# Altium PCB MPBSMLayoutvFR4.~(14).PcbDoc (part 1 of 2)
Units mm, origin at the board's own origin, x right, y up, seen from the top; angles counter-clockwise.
Board outline 131.7 x 110.39 mm, 4 copper layers (Top Layer, Power, GroundPlane, Bottom Layer), stack 2.286 mm thick; 156 components, 77 nets, 429 pads, 117 vias.
Unrouted connection lines stored in the file: 25.
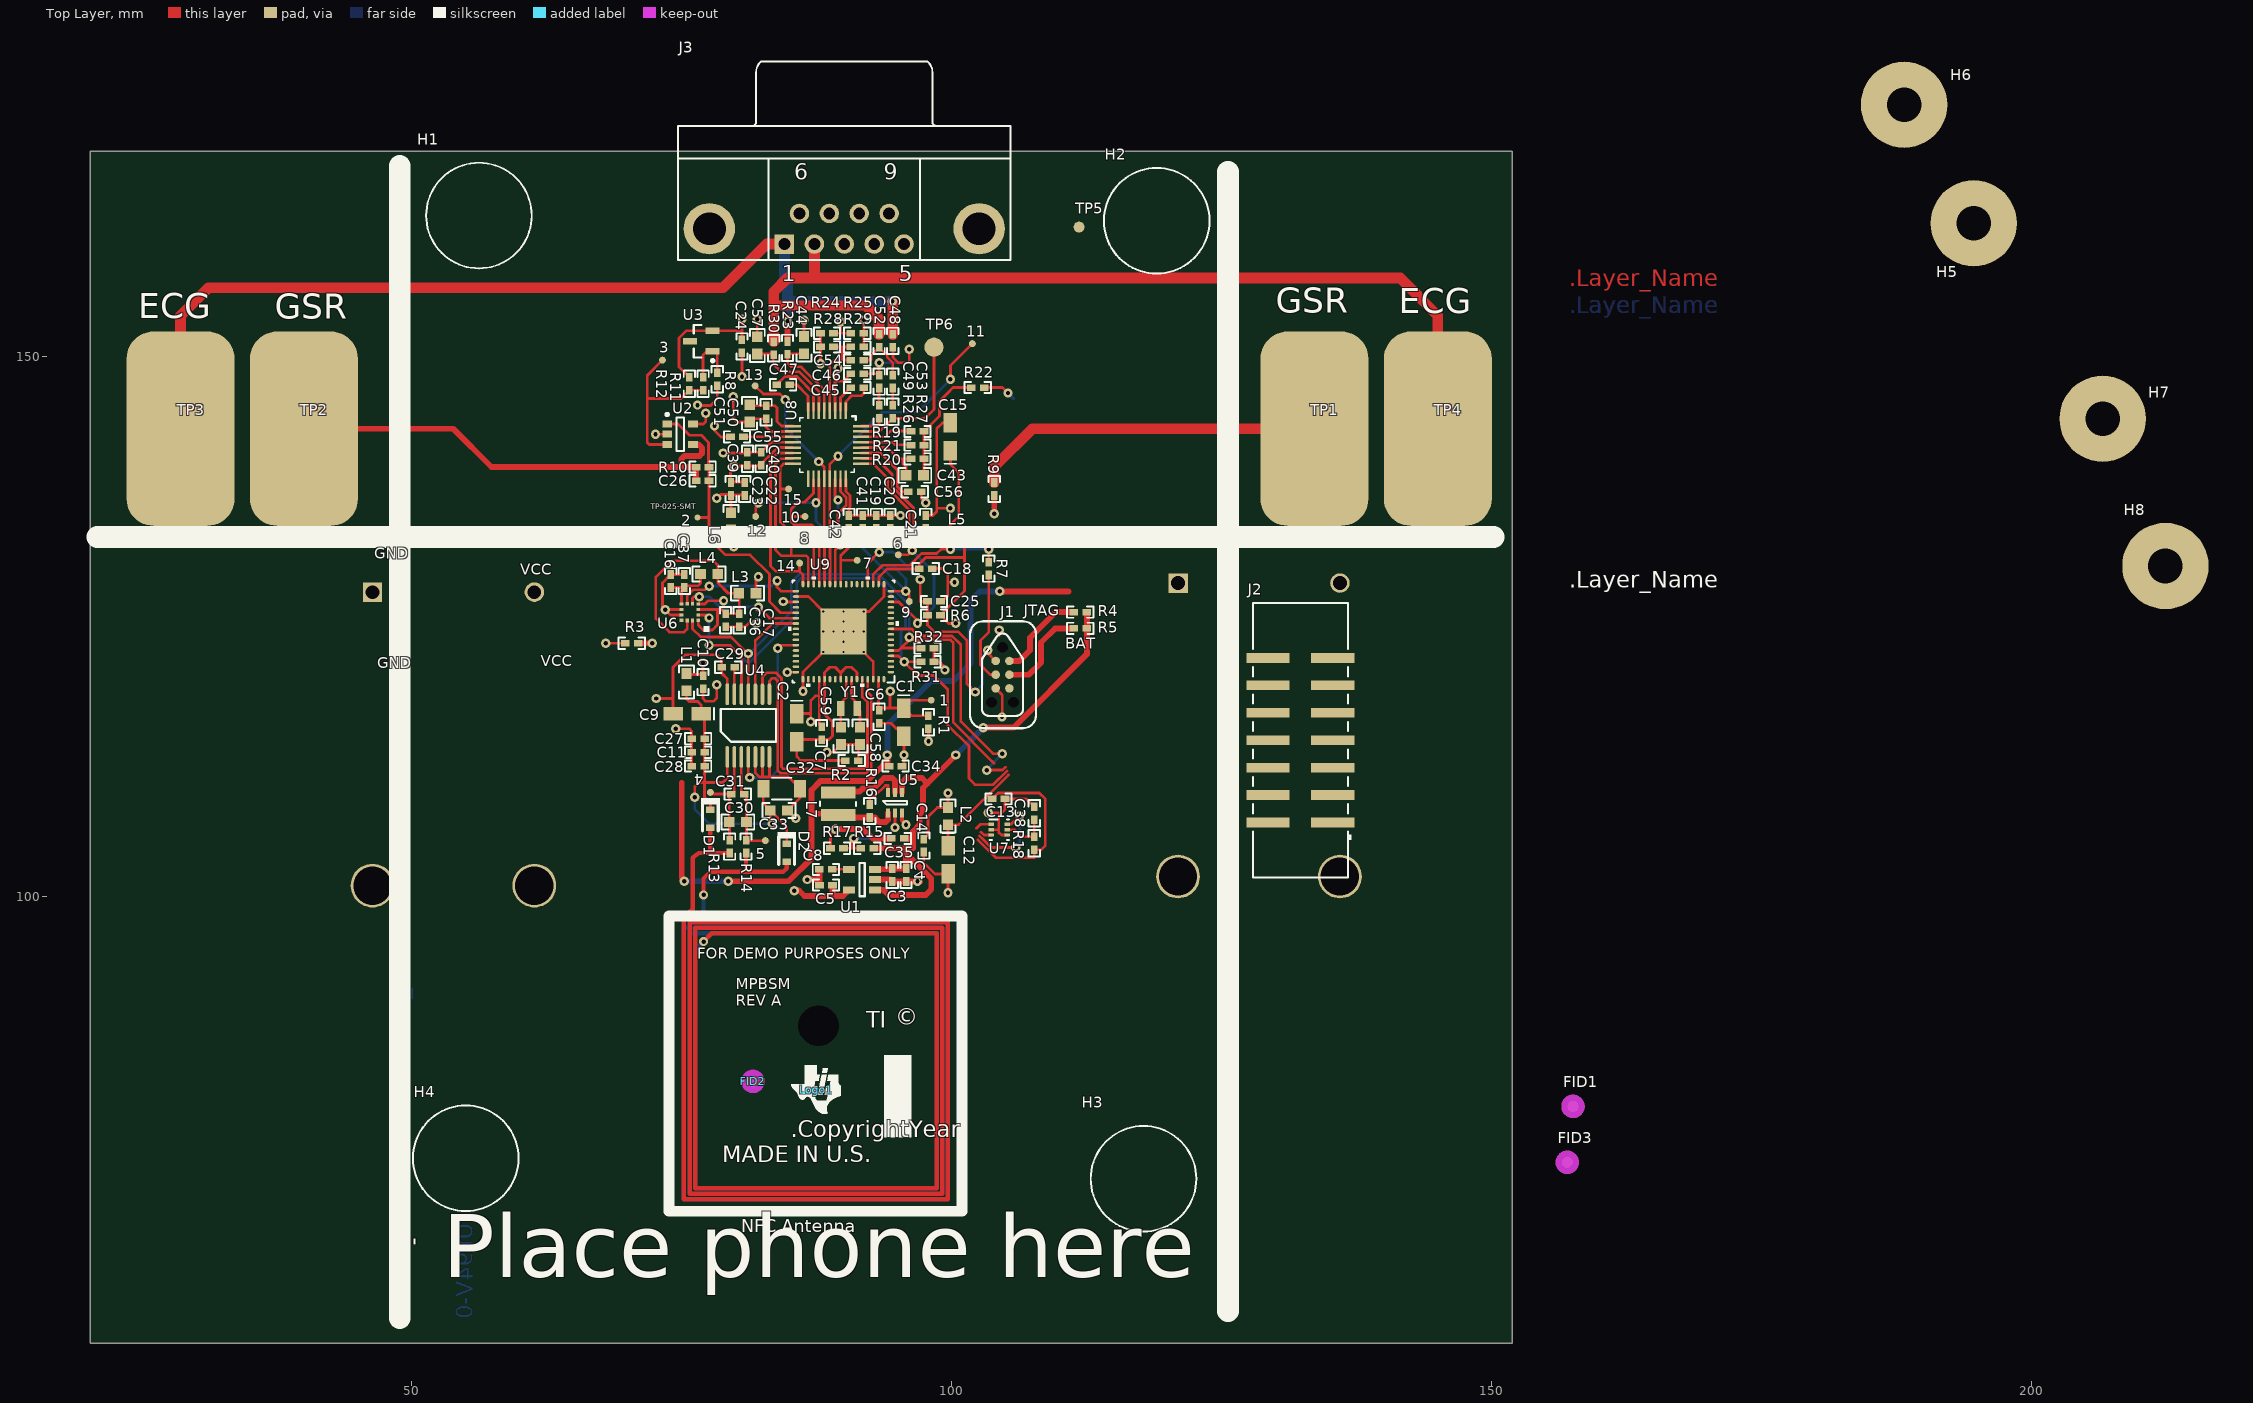
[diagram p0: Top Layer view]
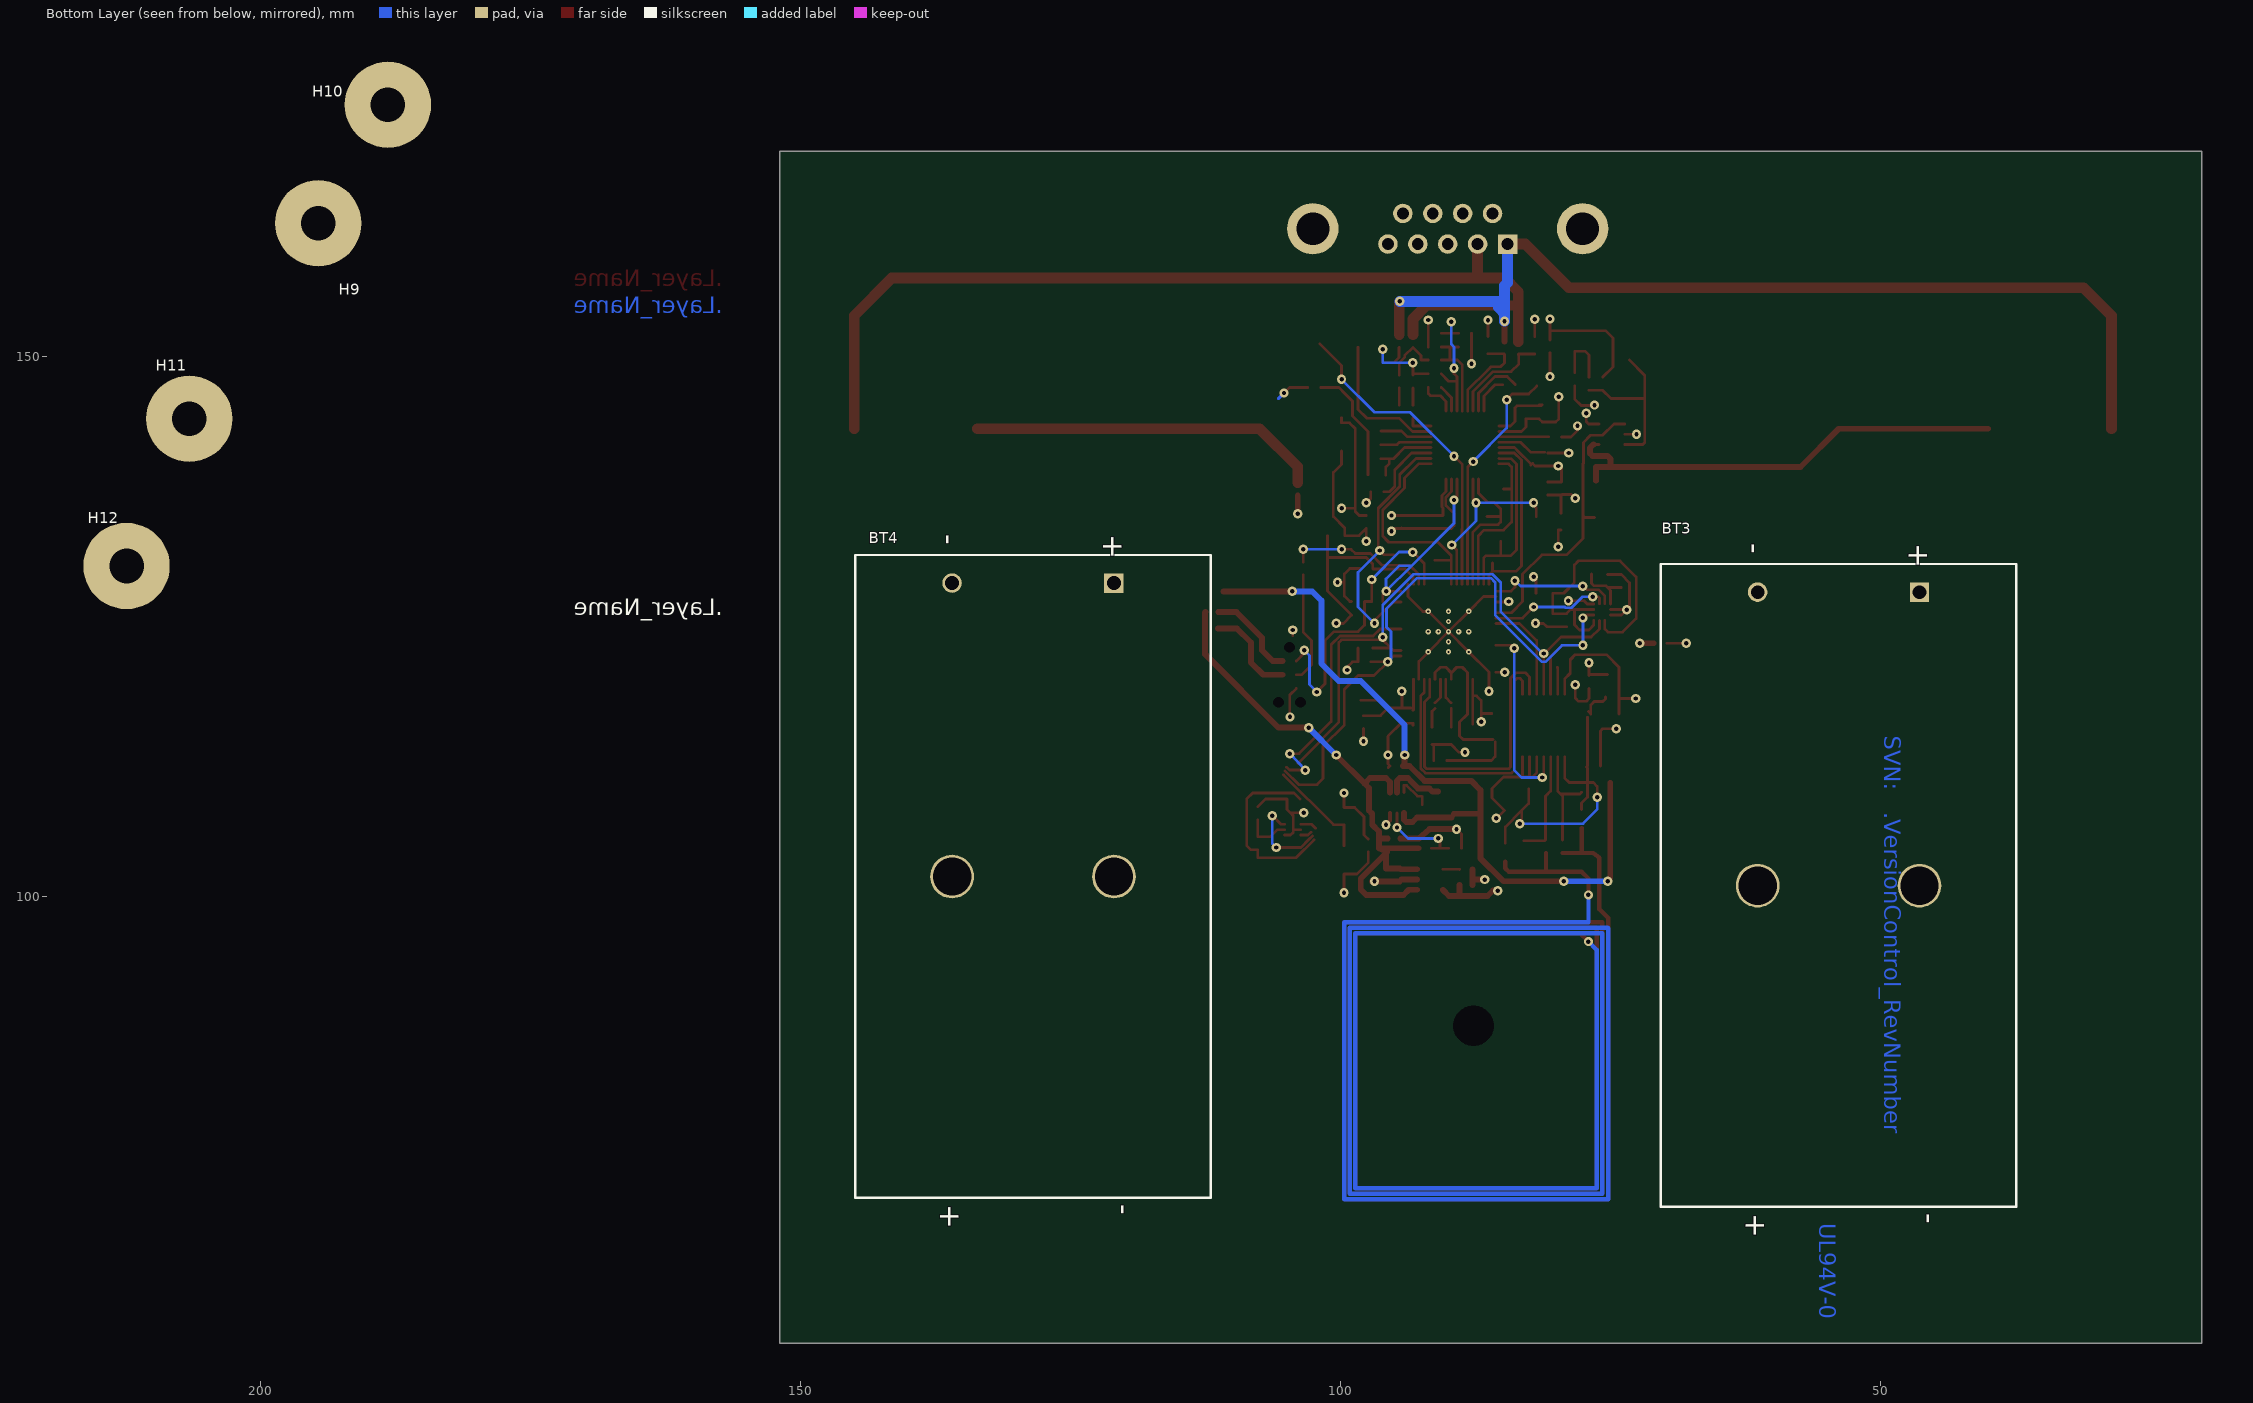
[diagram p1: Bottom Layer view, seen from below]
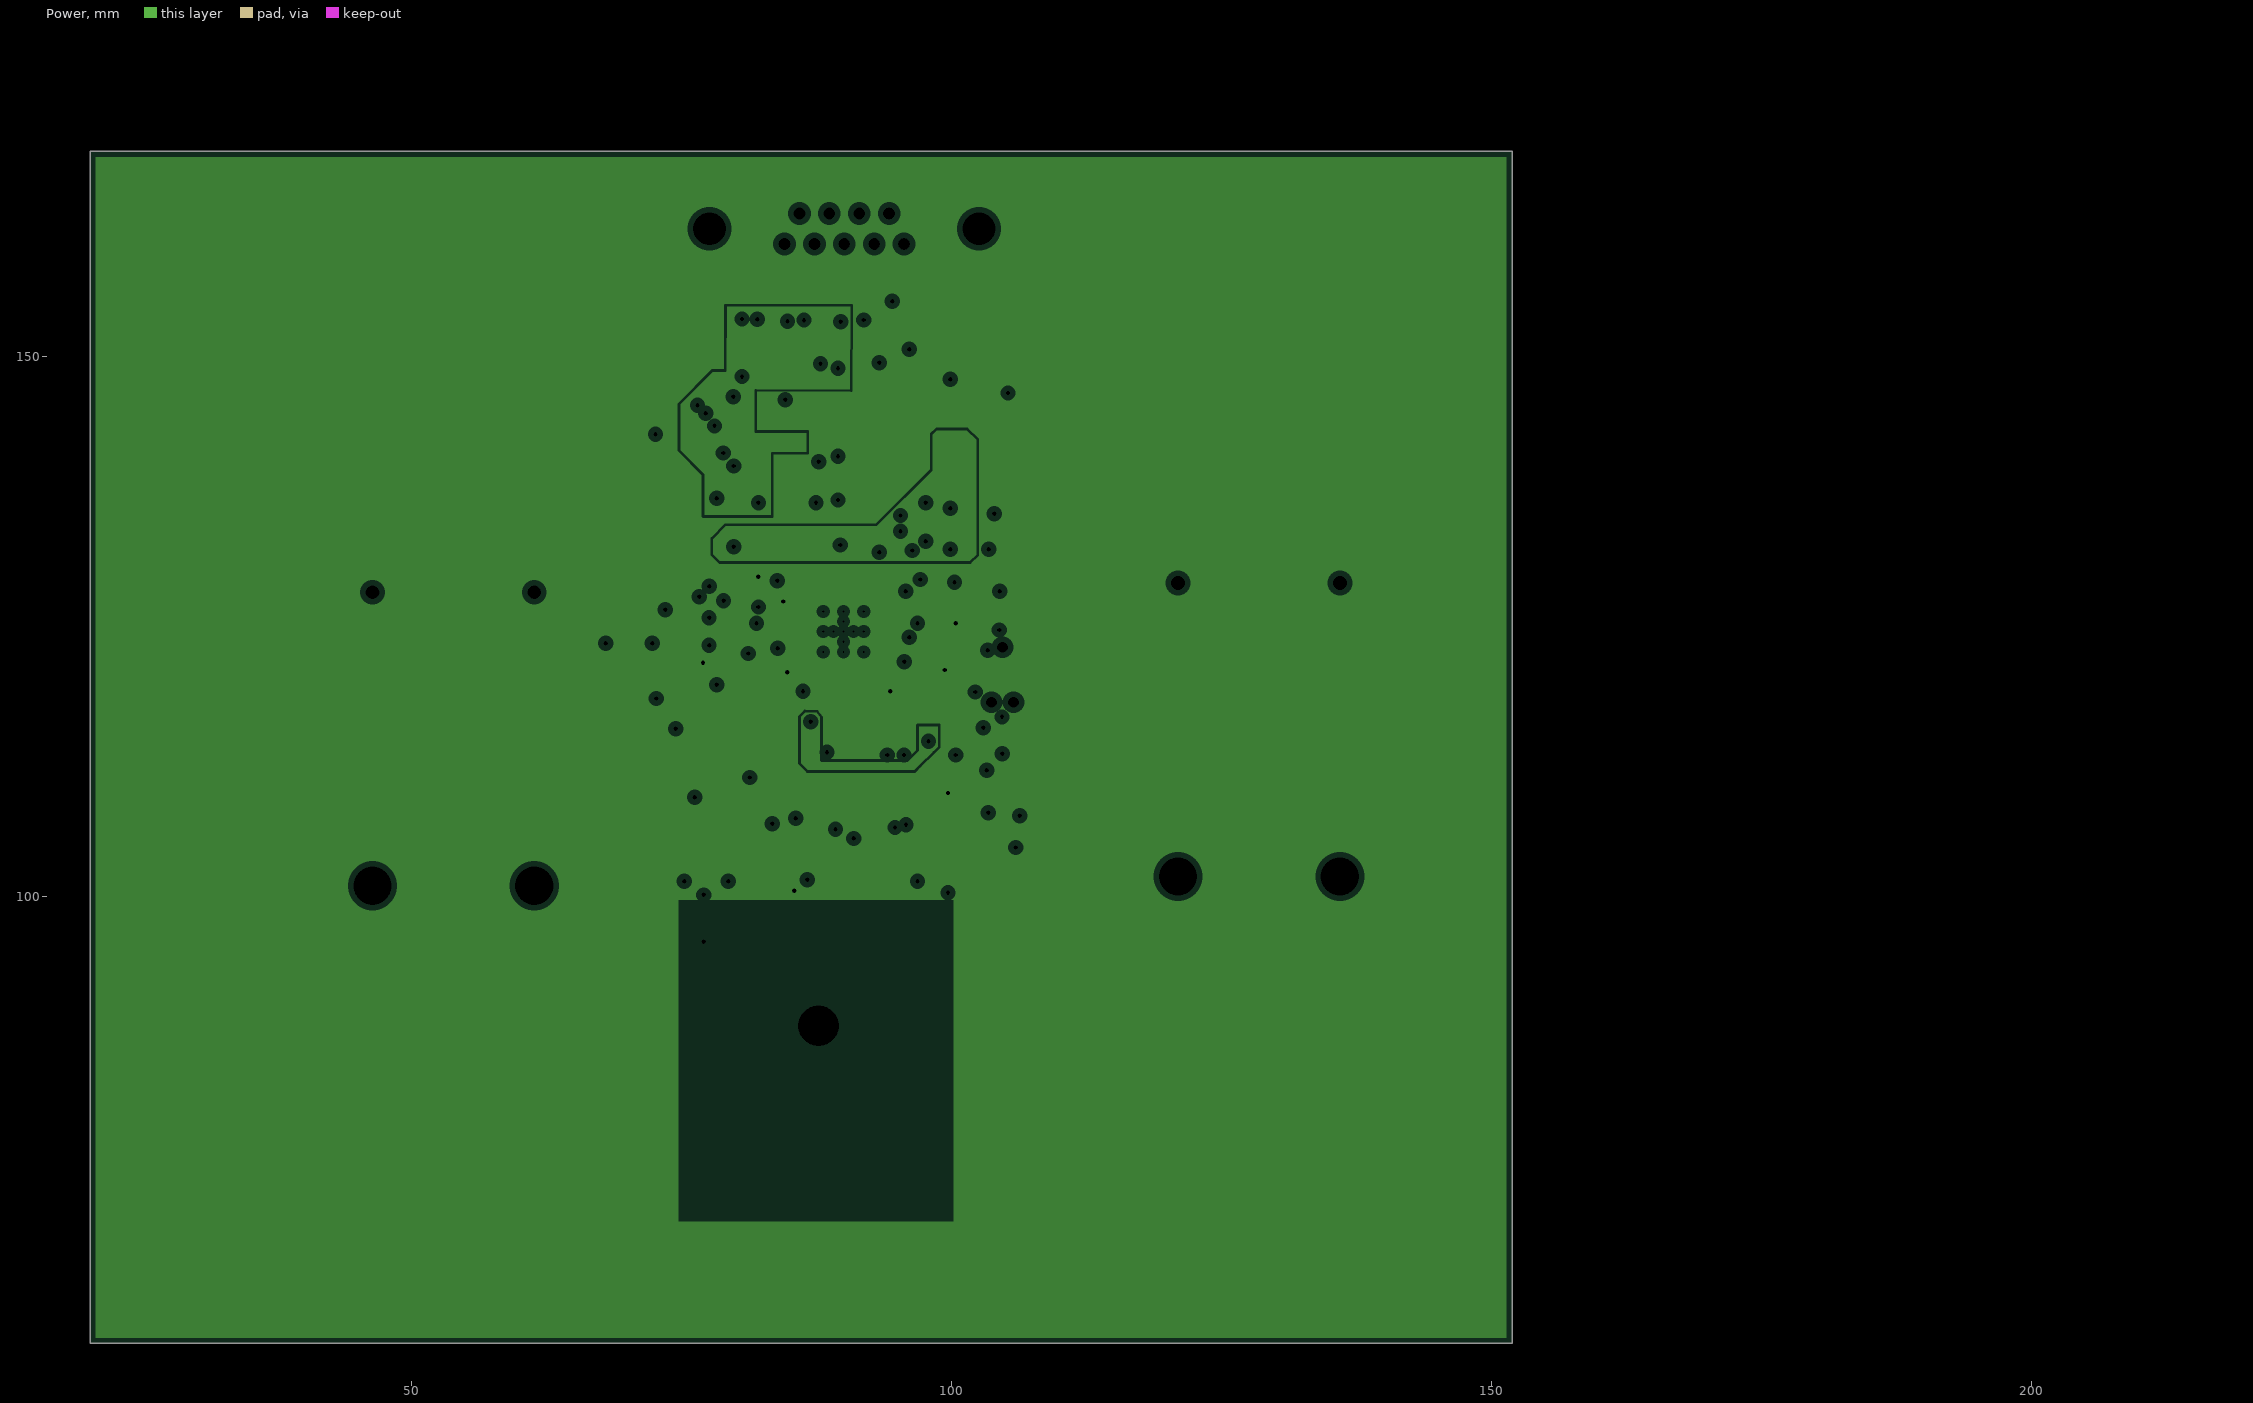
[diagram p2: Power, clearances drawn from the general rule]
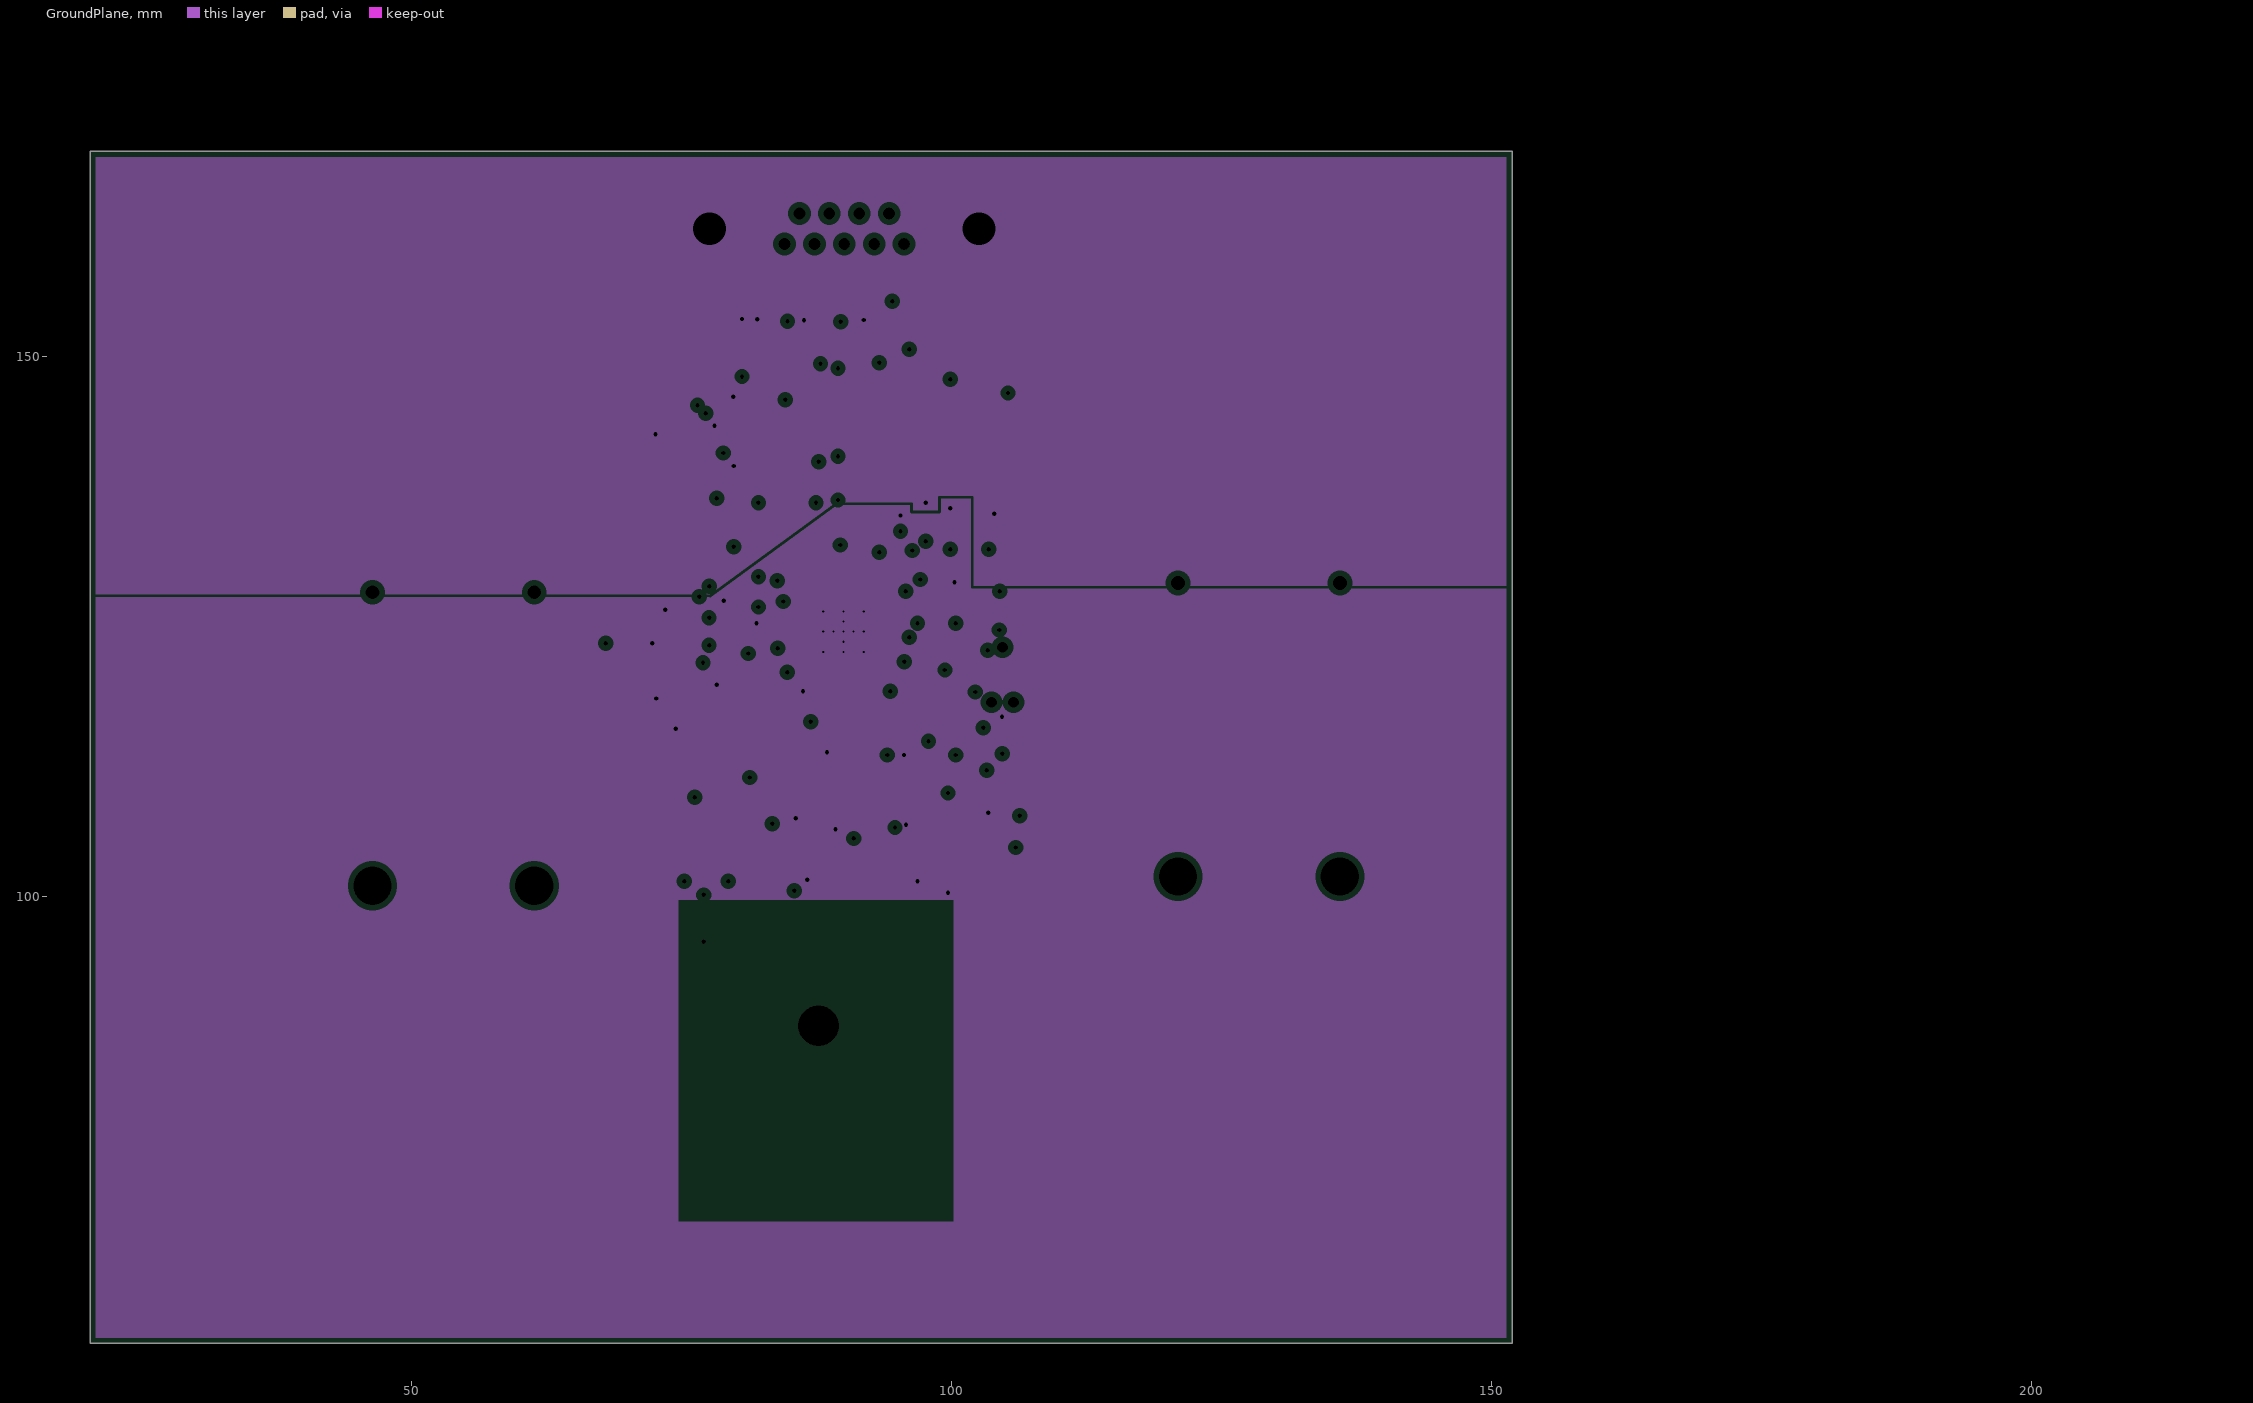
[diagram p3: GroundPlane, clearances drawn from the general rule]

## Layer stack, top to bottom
Top Solder: solder mask 0.0102, Solder Resist, Dk 3.5
Top Layer: signal copper 0.0356
Dielectric1: core 1.5037, FR-4, Dk 4.8
Power: plane copper 0.0356, net DVCC
Dielectric2: prepreg 0.32, FR-4, Dk 4.8
GroundPlane: plane copper 0.0356, net GND
Dielectric3: core 0.32, FR-4, Dk 4.8
Bottom Layer: signal copper 0.0356
Bottom Solder: solder mask 0.0102, Solder Resist, Dk 3.5

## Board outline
20.218,169.037 20.218,58.649 150.825,58.649 151.917,58.649 151.917,158.471 151.917,169.037 20.218,169.037

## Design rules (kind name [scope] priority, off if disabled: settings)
AcuteAngle [All] p1: minimum=4.50000000000000E+0001 checktracksonly=FALSE
AssemblyTestPointUsage [All] p1: valid=2
Clearance Clearance_BoardEdge_MountingHoles [OnCopper and InComponentClass('Mounting Holes') vs IsKeepOut] p1: gap=1.016
Clearance Clearance_BoardEdge_Poly [OnCopper and InPoly vs IsKeepOut] p2: gap=0.635
Clearance Clearance_BoardEdge [OnCopper and Not InComponentClass('Logo') and not InComponentClass('FiducialMark') and not InRegion(1000,500,4000,800) and Not IsKeepout vs IsKeepOut] p3: gap=1.905
Clearance Clearance_Poly [InPolygon] p4: gap=0.635
Clearance [All] p5: gap=0.1
ComponentClearance ComponentClearance_Shunt [InComponentClass('Header') vs InComponentClass('Shunt')] p1: gap=0 collisioncheckmode=3 verticalgap=0 showdistances=FALSE
ComponentClearance ComponentClearance_MountingHoles_FiducialMarks [InComponentClass('Mounting Holes') vs InComponentClass('FiducialMark')] p2: gap=1.27 collisioncheckmode=3 verticalgap=0.254 showdistances=FALSE
ComponentClearance ComponentClearance_Logo [InComponentClass('Logo')] p3: gap=1.27 collisioncheckmode=3 verticalgap=0.254 showdistances=FALSE
ComponentClearance ComponentClearance_ScrewToNut [(HasFootprint('NY PMS 440 0025 PH')) vs (HasFootprint('Keystone_1902C'))] p4: gap=0.127 collisioncheckmode=3 verticalgap=0.254 showdistances=FALSE
ComponentClearance ComponentClearance_MountingHoles [InComponentClass('Mounting Holes')] p5: gap=6.35 collisioncheckmode=3 verticalgap=2540 showdistances=FALSE
ComponentClearance ComponentClearance_SmallPassives [HasFootprint('0201*') or HasFootprint('0402*') or HasFootprint('0508') or HasFootprint('0603*') or HasFootprint('0612') or HasFootprint('0805*') or HasFootprint('0815*') or HasFootprint('0830*') or HasFootprint('1206*') or HasFootprint('1210*') or HasFootprint('1808*') or HasFootprint('1812*') or HasFootprint('1825*') or HasFootprint('2010*') or HasFootprint('2220*') or HasFootprint('2225*') or HasFootprint('2512*') or HasFootprint('2728*') or HasFootprint('3518*') vs HasFootprint('0201*') or HasFootprint('0402*') or HasFootprint('0508') or HasFootprint('0603*') or HasFootprint('0612') or HasFootprint('0805*') or HasFootprint('0815*') or HasFootprint('0830*') or HasFootprint('1206*') or HasFootprint('1210*') or HasFootprint('1808*') or HasFootprint('1812*') or HasFootprint('1825*') or HasFootprint('2010*') or HasFootprint('2220*') or HasFootprint('2225*') or HasFootprint('2512*') or HasFootprint('2728*') or HasFootprint('3518*')] p6: gap=0.508 collisioncheckmode=3 verticalgap=0.254 showdistances=FALSE
ComponentClearance ComponentClearance_THtoSMT [IsThruComponent vs IsSMTComponent] p7: gap=2.54 collisioncheckmode=3 verticalgap=0.762 showdistances=FALSE
ComponentClearance ComponentClearance_THtoTH [IsThruComponent vs IsThruComponent] p8: gap=3 collisioncheckmode=3 verticalgap=0.762 showdistances=FALSE
ComponentClearance [All] p9: gap=1.016 collisioncheckmode=3 verticalgap=0.254 showdistances=FALSE
DiffPairsRouting [All] p1: maxlimit=2.54 minlimit=0.254 mostfreqgap=0.254 toplayer_minwidth=0.381 toplayer_maxwidth=0.381 toplayer_prefwidth=0.381 bottomlayer_minwidth=0.381 bottomlayer_maxwidth=0.381 bottomlayer_prefwidth=0.381 maxuncoupledlength=25.4
FabricationTestPointUsage TestPointUsage [All] p1: valid=2 allowmultiple=FALSE
FabricationTestpoint Testpoint [All] p1: side=3 testpointundercomponent=TRUE minsize=1.016 maxsize=2.54 preferedsize=1.524 minholesize=0 maxholesize=1.016 preferedholesize=0.813 testpointgrid=0.025 allowsidetop=TRUE allowsidebottom=TRUE usegrid=TRUE gridtolerance=0
FanoutControl Fanout_LCC [IsLCC] p1: bgadir=Out bgaviamode=Centered fanoutstyle=Auto fanoutdirection=Alternating viagrid=0.025 // Fanout_LCC (Default Rule)
FanoutControl Fanout_BGA [IsBGA] p2: bgadir=Out bgaviamode=Centered fanoutstyle=Auto fanoutdirection=Alternating viagrid=0.025 // Fanout_BGA (Default Rule)
FanoutControl Fanout_Default [All] p4: bgadir=Out bgaviamode=Centered fanoutstyle=Auto fanoutdirection=Alternating viagrid=0.025 // Fanout_Default (Default Rule)
FanoutControl Fanout_Small [(CompPinCount < 5)] p5: bgadir=Out bgaviamode=Centered fanoutstyle=Auto fanoutdirection=OutThenIn viagrid=0.025 // Fanout_Small (Default Rule)
Height [All] p1: minheight=0 maxheight=55.4 prefheight=12.7
HoleSize [All] p1: absolutevalues=TRUE maxlimit=6.375 minlimit=0.1 maxpercent=80.000 minpercent=20.000
MinimumAnnularRing MinimumAnnularRing_ThermalPadVias [IsVia and InAnyComponent] p1: minimumring=0.15
MinimumAnnularRing [All] p2: minimumring=0.229
MinimumSolderMaskSliver MinimumSolderMaskSliver_Logo [InComponentClass('Logo') vs InComponentClass('Logo')] p1: minsoldermaskwidth=0.018
MinimumSolderMaskSliver [All] p2: minsoldermaskwidth=0.08
PlaneClearance [All] p1: clearance=0.508
PlaneConnect [All] p1: planeconnectstyle=Relief reliefexpansion=0.254 reliefentries=4 reliefconductorwidth=0.254 reliefairgap=0.254
PolygonConnect [All] p1: connectstyle=Relief reliefconductorwidth=0.254 reliefentries=4 polygonreliefangle="90 Angle" airgapwidth=0.254
RoutingVias ThermalPadVias [IsVia and InAnyComponent] p1: holewidth=0.2 width=0.5 viastyle="Through Hole" minholewidth=0.2 minwidth=0.5 maxholewidth=0.33 maxwidth=0.6
RoutingVias [All] p2: holewidth=0.406 width=0.864 viastyle="Through Hole" minholewidth=0.2 minwidth=0.66 maxholewidth=1.016 maxwidth=1.651
SMDToCorner [All] p1: distance=30000
SilkToSilkClearance SilkToSilkClearance_Pb-FreeLogo [(HasFootprint('Pb-Free_Overlay_Medium') OR HasFootprint('Pb-Free_Overlay_Small')) vs (HasFootprint('Pb-Free_Overlay_Medium') OR HasFootprint('Pb-Free_Overlay_Small'))] p1: silktosilkclearance=0
SilkToSilkClearance [All] p2: silktosilkclearance=0
SilkToSolderMaskClearance SilkscreenOverComponentPads [IsPad] p1: minsilkscreentomaskgap=0.127 clearancetoexposedcopper=TRUE
SolderMaskExpansion [All] p1: expansion=0.05
Width [All] p1: maxlimit=2.54 minlimit=0.152 preferedwidth=0.254 checkconnectedcopper=TRUE
14 further rules are at their usual default settings.

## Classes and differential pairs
component class Logo: Logo1
component class Designator: FID1 FID2 FID3 H1 H2 H3 H4 H5 H6 H7 H8 H9 H10 H11 H12 Logo1 ZZ1 ZZ2 ZZ3 ZZ4
component class FiducialMark: FID1 FID2 FID3
component class AssemblyNote: ZZ1 ZZ2 ZZ3 ZZ4
component class Battery: BT3 BT4 U?
component class BMA280: C36 C37 U6
component class "Boost Converter": C34 C35 L7 R15 R16 R17 U5
component class ECG: 6 7 8 9 10 11 12 13 14 15 C39 C40 C41 C42 C43 C44 C45 C46 C47 C48 C49 C50 C51 C52 C53 C54 C55 C56 C57 R19 R20 R21 R22 R23 R24 R25 R26 R27 R28 R29 R30 TP6 U8
component class GSR: 2 3 C26 R8 R9 R10 R11 R12 U2 U3
component class "JTAG SPY-BY-WIRE": C25 J1 J2 R4 R5 R6 R7
component class MSP430FR5XXX: C58 C59 R31 R32 U9 Y1
component class "Power Filtering": 1 C1 C2 C3 C4 C5 C6 C7 C8 C9 C10 C11 C12 C13 C14 C15 C16 C17 C18 C19 C20 C21 C22 C23 C24 L1 L2 L3 L4 L5 L6 R1 R2 R3 U1
component class Temperature: C38 R18 U7
component class Transponder: 4 5 C27 C28 C29 C30 C31 C32 C33 D1 D2 R13 R14 U4
component class "Analog Connector": J3
component class "Mounting Holes": H5 H6 H7 H8

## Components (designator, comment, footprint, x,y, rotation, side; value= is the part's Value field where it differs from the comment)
1 "TP-025-SMT" TP_25MIL-SMT#1 98.12,118.212 r90 top
2 "TP-025-SMT" TP_25MIL-SMT#2 76.479,135.128 r0 top
3 "TP-025-SMT" TP_25MIL-SMT#1 73.228,149.708 r0 top
4 "TP-025-SMT" TP_25MIL-SMT#1 77.669,109.676 r0 top
5 "TP-025-SMT" TP_25MIL-SMT#1 82.753,105.207 r270 top
6 "TP-025-SMT" TP_25MIL-SMT#1 95.072,131.674 r0 top
7 "TP-025-SMT" TP_25MIL-SMT#1 91.262,131.166 r0 top
8 "TP-025-SMT" TP_25MIL-SMT#1 85.166,133.198 r0 top
9 "TP-025-SMT" TP_25MIL-SMT#1 96.088,127.356 r0 top
10 "TP-025-SMT" TP_25MIL-SMT#1 86.436,135.23 r0 top
11 "TP-025-SMT" TP_25MIL-SMT#1 101.93,151.232 r0 top
12 "TP-025-SMT" TP_25MIL-SMT#1 81.864,135.23 r0 top
13 "TP-025-SMT" TP_25MIL-SMT#1 81.813,147.32 r0 top
14 "TP-025-SMT" TP_25MIL-SMT#1 85.928,130.912 r90 top
15 "TP-025-SMT" TP_25MIL-SMT#1 84.912,137.77 r0 top
BT3 "2462" Keystone_2462 53.873,114.63 r270 bottom
BT4 "2462" Keystone_2462 128.473,115.468 r270 bottom
C1 "293D106X9010A2TE3" 3216-18 95.58,116.18 r270 top
C2 "293D106X9010A2TE3" 3216-18 85.674,115.672 r270 top
C3 "C1005X5R1A104K" 0402 94.518,102.028 r270 top
C4 "C1005X5R0J105M" 0402 95.788,102.028 r270 top
C5 "C1005X5R1C225K050BC" 0402 88.371,101.092 r180 top
C6 "C1005X5R1A104K" 0402 93.294,116.688 r270 top
C7 "C1005X5R1A104K" 0402 87.96,115.164 r270 top
C8 "C1005X7R1E103K" 0402 88.367,102.54 r180 top
C9 "293D105X9016A2TE3" 3216-18 75.514,116.942 r180 top
C10 "C1005X5R1A104K" 0402 76.987,119.888 r270 top
C11 "C1005X5R1A104K" 0402 76.53,113.386 r180 top
C12 "293D106X9010A2TE3" 3216-18 99.677,103.422 r270 top
C13 "C1005X5R1A104K" 0402 104.353,109.068 r0 top
C14 "C1005X5R1A104K" 0402 97.437,104.75 r270 top
C15 "293D105X9016A2TE3" 3216-18 99.898,142.596 r90 top
C16 "CL05A106MQ5NUNC" 0402 73.99,129.247 r90 top
C17 "CL05A106MQ5NUNC" 0402 80.34,125.624 r270 top
C18 "C1005X5R1A104K" 0402 97.612,130.404 r0 top
C19 "C1005X5R1A104K" 0402 93.04,134.722 r90 top
C20 "C1005X5R1C225K050BC" 0402 94.31,134.722 r90 top
C21 "CL05A106MQ5NUNC" 0402 97.612,134.722 r90 top
C22 "CL05A106MQ5NUNC" 0402 80.848,137.77 r90 top
C23 "C1005X5R1A104K" 0402 79.578,137.77 r90 top
C24 "C1005X5R1A104K" 0402 80.594,150.978 r90 top
C25 "C1005X8R1H222K" 0402 98.374,127.356 r0 top
C26 "C1005X7R1E103K" 0402 76.946,138.532 r180 top
C27 "C1005X5R0J105M" 0402 76.53,114.656 r180 top
C28 "C1005X5R1A104K" 0402 76.53,112.116 r180 top
C29 "GRM155R60J474KE19D" 0402 79.324,121.26 r0 top
C30 "C1608C0G1H330J" 0603 80.209,106.941 r0 top
C31 "GRM1555C1H390JA01D" 0402 80.209,109.515 r0 top
C32 "C3216X5R1A107M160AC" 1206_190 84.273,110.023 r0 top
C33 "Used in BOM report" 0603 84.019,107.991 r0 top
C34 "CL05A106MQ5NUNC" 0402 94.818,112.116 r0 top
C35 "CL05A106MQ5NUNC" 0402 95.021,105.41 r180 top
C36 "C1005X5R1A104K" 0402 79.07,125.624 r270 top
C37 "C1005X5R1A104K" 0402 75.26,129.247 r90 top
C38 "C1005X7R1E103K" 0402 107.655,107.752 r90 top
C39 "C1005X5R1C105K050BC" 0402 81.102,140.564 r270 top
C40 "C1005X5R1A104K" 0402 82.372,140.564 r270 top
C41 "C1005X5R1C105K050BC" 0402 91.77,134.722 r90 top
C42 "C1005X5R1A104K" 0402 90.5,134.722 r90 top
C43 "C0603C152K5RACTU" 0603 96.596,139.04 r180 top
C44 "GRM1885C1H302JA01D" 0603 86.335,151.091 r90 top
C45 "GRM155R61A472KA01D" 0402 91.262,147.168 r0 top
C46 "C1005X8R1H222K" 0402 91.262,148.438 r0 top
C47 "GRM155R61A472KA01D" 0402 84.404,147.422 r180 top
C48 "C1005X5R1A104K" 0402 94.564,151.486 r270 top
C49 "C1005X8R1H222K" 0402 93.294,147.722 r90 top
C50 "C1005X5R1A104K" 0402 82.829,144.872 r270 top
C51 "C1608X5R0J106M" 0603 81.305,144.78 r270 top
C52 "C1005X5R1A104K" 0402 93.294,151.486 r270 top
C53 "C1005X8R1H222K" 0402 94.564,147.722 r90 top
C54 "C1005X8R1H222K" 0402 91.262,149.708 r0 top
C55 "C1005X5R1C105K050BC" 0402 80.132,142.596 r180 top
C56 "C1005X5R1C105K050BC" 0402 96.596,137.516 r0 top
C57 "GRM1885C1H302JA01D" 0603 82.013,151.063 r90 top
C58 "06035A100JAT2A" 0603 91.516,114.91 r270 top
C59 "06035A100JAT2A" 0603 89.764,114.91 r270 top
D1 "CDBU0130L" SOD-523F 77.669,107.229 r270 top
D2 "CDBU0130L" SOD-523F 84.734,104.089 r270 top
FID1 "Fiducial" Fiducial10-20 157.556,80.594 r0 top
FID2 "Fiducial" Fiducial10-20 81.61,82.906 r0 top
FID3 "Fiducial" Fiducial10-20 157.023,75.413 r0 top
H1 "SJ61A2" Bumpon_SJ61A2 56.236,163.093 r0 top
H2 "SJ61A2" Bumpon_SJ61A2 118.999,162.611 r0 top
H3 "SJ61A2" Bumpon_SJ61A2 117.78,73.889 r0 top
H4 "SJ61A2" Bumpon_SJ61A2 55.016,75.794 r0 top
H5 "NY PMS 440 0025 PH" "NY PMS 440 0025 PH" 194.666,162.382 r90 top
H6 "NY PMS 440 0025 PH" "NY PMS 440 0025 PH" 188.214,173.355 r90 top
H7 "NY PMS 440 0025 PH" "NY PMS 440 0025 PH" 206.604,144.272 r90 top
H8 "NY PMS 440 0025 PH" "NY PMS 440 0025 PH" 212.421,130.638 r90 top
H9 "1902C" Keystone_1902C 194.665,162.376 r90 bottom
H10 "1902C" Keystone_1902C 188.239,173.33 r90 bottom
H11 "1902C" Keystone_1902C 206.604,144.272 r90 bottom
H12 "1902C" Keystone_1902C 212.42,130.632 r180 bottom
J1 "TC2030-MCP-NL" TC2030-MCP-NL 104.724,120.574 r180 top
J2 "61201420621" Wurth_61201420621 132.309,114.503 r180 top
J3 "182-009-213R171" NORCOMP_182-009-213R171 90.068,171.374 r0 top
L1 "BLM18HG601SN1D" 0603 75.463,119.888 r270 top
L2 "BLM18HG601SN1D" 0603 99.677,107.486 r270 top
L3 "BLM18HG601SN1D" 0603 81.102,128.118 r180 top
L4 "BLM18HG601SN1D" 0603 77.546,129.896 r0 top
L5 "BLM18HG601SN1D" 0603 100.406,133.452 r180 top
L6 "BLM18HG601SN1D" 0603 79.578,134.772 r90 top
L7 "EPL3015-472MLB" EPL3015 89.51,108.61 r90 top
Logo1 "Texas Instruments" TI_Symbol_Overlay_Small 87.452,82.144 r0 top
R1 "ERJ-2GE0R00X" 0402 97.866,116.18 r270 top
R2 "ERJ-2GE0R00X" 0402 90.754,112.624 r180 top
R3 "ERJ-2GE0R00X" 0402 70.393,123.489 r180 top
R4 "ERJ-2GE0R00X" 0402 111.912,126.365 r0 top
R5 "ERJ-2GE0R00X" 0402 111.932,124.861 r0 top
R6 "CRCW040247K0JNED" 0402 98.374,126.086 r0 top
R7 "ERJ-2GE0R00X" 0402 103.454,130.404 r90 top
R8 "CRCW040221K5FKED" 0402 78.308,147.93 r270 top
R9 "CRCW040210K0FKED" 0402 103.962,137.77 r90 top
R10 "ERJ-2RKF1004X" 0402 76.946,139.802 r0 top
R11 "CRCW040211K8FKED" 0402 76.993,147.517 r90 top
R12 "CRCW04028K06FKED" 0402 75.723,147.517 r270 top
R13 "ERJ-2GE0R00X" 0402 79.447,104.655 r270 top
R14 "ERJ-2GE0R00X" 0402 80.971,104.655 r270 top
R15 "ERJ-2RKF1004X" 0402 92.186,104.496 r0 top
R16 "ERJ-2GE0R00X" 0402 92.431,107.95 r90 top
R17 "ERJ-2RKF2003X" 0402 89.392,104.496 r0 top
R18 "CRCW04024K99FKED" 0402 107.655,104.958 r270 top
R19 "ERJ-2GE0R00X" 0402 96.85,143.104 r0 top
R20 "ERJ-2RKF1004X" 0402 96.85,140.564 r0 top
R21 "ERJ-2RKF1003X" 0402 96.85,141.834 r0 top
R22 "ERJ-2RKF1003X" 0402 102.438,147.168 r0 top
R23 "CRCW040251K1FKED" 0402 84.811,150.837 r270 top
R24 "CRCW040210M0FKED" 0402 88.468,152.202 r180 top
R25 "CRCW040210M0FKED" 0402 91.262,152.202 r180 top
R26 "CRCW040240K2FKED" 0402 93.294,144.928 r270 top
R27 "CRCW040240K2FKED" 0402 94.564,144.928 r270 top
R28 "CRCW040210M0FKED" 0402 88.468,150.932 r180 top
R29 "CRCW040210M0FKED" 0402 91.262,150.932 r180 top
R30 "CRCW040251K1FKED" 0402 83.537,150.809 r270 top
R31 "CRCW04023K30JNED" 0402 97.774,121.768 r180 top
R32 "CRCW04023K30JNED" 0402 97.774,123.038 r180 top
TP1 "TESTPOINT" TP_SM_1MM#1 133.604,143.358 r0 top
TP2 "TESTPOINT" TP_SM_1MM#2 40.03,143.358 r90 top
TP3 "TESTPOINT" TP_SM_1MM#2 28.6,143.358 r90 top
TP4 "TESTPOINT" TP_SM_1MM#2 145.034,143.358 r90 top
TP5 "TESTPOINT" TP_SM_1MM#3 111.811,162.027 r90 top
TP6 "Pogo Pad" PogoPad 98.374,150.901 r0 top locked
U1 "TPS73030DBVR" DBV0005A_N 91.719,101.6 r180 top
U2 "LMP2231AMFE" MF05A_L 74.868,142.85 r0 top
U3 "LM4041AIM3-1.2" MF03A_N 76.835,151.46 r180 top
U4 "RF430CL331HCPW" PW0014A_M 81.185,115.864 r90 top
U5 "TPS61220DCK" DCK0006A_N 94.767,108.712 r90 top
U6 "BMA280" LGA-12P 75.768,126.361 r90 top
U7 "TMP112AIDRL" DRL0006A 104.427,106.221 r0 top
U8 "ADS1292RIPBS" PBS0032A_N 88.468,141.853 r270 top
U9 "MSP430FR5889IRGCR" RGC0064B 89.992,124.562 r180 top
Y1 "FC-12M 32.7680KA-A3" Epson_FC-12M 90.5,117.45 r0 top
ZZ1 "This Assembly Note is for PCB labels only" AssemblyNoteLabel 35.992,195.631 r0 top
ZZ2 "These assemblies are ESD sensitive, ESD precautions shall be observed." AssemblyNote 35.992,192.865 r0 top
ZZ3 "These assemblies must be clean and free from flux and all contaminants. Use of no clean flux is not acceptable." AssemblyNote 35.992,190.616 r0 top
ZZ4 "These assemblies must comply with workmanship standards IPC-A-610 Class 2, unless otherwise specified." AssemblyNote 35.992,188.366 r0 top

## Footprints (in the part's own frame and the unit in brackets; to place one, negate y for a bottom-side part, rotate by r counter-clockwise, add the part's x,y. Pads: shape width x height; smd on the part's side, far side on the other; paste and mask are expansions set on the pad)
0402 [mm] "0402 from SM-752 data"
  rect 0.8x0.6 smd: 1(-0.6,0) 2(0.6,0)
  silkscreen extent -1.22,-0.52 1.22,0.52, body extent -0.55,-0.3 0.55,0.3, height 0.6
0603 [mm] "0603 from SM-752 data"
  rect 1x0.95 smd: 1(-0.8,0) 2(0.8,0)
  silkscreen extent -1.52,-0.69 1.52,0.69, body extent -0.87,-0.47 0.87,0.47, height 0.85
1206_190 [mm] "1206_190"
  rect 1.1x1.6 smd: 1(-1.7,0) 2(1.7,0)
  silkscreen extent -0.9,-1 0.9,1, body extent -1.75,-0.95 1.75,0.95, height 1.9
3216-18 [mm] "Medium density IPC, based on Kemet T495 dimensions"
  rect 1.8x1.25 smd: 1(-1.3,0) 2(1.3,0)
  silkscreen extent -2.49,-0.54 -2.49,0.54, body extent -1.7,-0.9 1.7,0.9, height 1.8
AssemblyNote [mm] "Assembly Note"
AssemblyNoteLabel [mm] "Assembly Note for PCB Labels"
Bumpon_SJ61A2 [mil] "3M Hemispherical Bumpon transparent"
  round 1 on Mech3: 0(0,0)
  silkscreen extent -192,-192 192,192, body extent -191,-192 193,192, height 250
DBV0005A_N [mm] "SOT23, 5-Leads, Body 2.9x1.6mm, Pitch 0.95mm, Lead Span 2.8mm, IPC Medium Density"
  rect 1.1x0.65 smd: 1(-1.2,0.95) 2(-1.2,0) 3(-1.2,-0.95) 4(1.2,-0.95) 5(1.2,0.95)
  silkscreen extent -0.25,-1.55 0.25,1.55, body extent -1.42,-1.46 1.42,1.46, height 1.08
DCK0006A_N [mm] "SOT23, 6-Leads, Body 2x1.3mm, Pitch 0.65mm, Lead Span 2.1mm, IPC Medium Density"
  rect 0.85x0.4 smd: 1(-0.95,0.65) 2(-0.95,0) 3(-0.95,-0.65) 4(0.95,-0.65) 5(0.95,0) 6(0.95,0.65)
  silkscreen extent -0.15,-1.1 0.15,1.1, body extent -1.14,-1 1.14,1, height 0.94
DRL0006A [mm] "SOTFL, 6-Flat Leads, Body 1.2x1.6x0.6mm, Pitch 0.5mm, TI recommended"
  rect 0.5x0.3 smd: 1(-0.75,0.5) 2(-0.75,0) 3(-0.75,-0.5) 4(0.75,-0.5) 5(0.75,0) 6(0.75,0.5)
  silkscreen extent -0.9,-0.95 0.9,0.95, body extent -0.85,-0.85 0.85,0.85, height 0.62
EPL3015 [mm] "COILCRAFT"
  rect 1.12x3.2 smd: 1(-1.04,0) 2(1.04,0)
  silkscreen extent -0.22,-1.65 0.23,1.68, body extent -1.6,-1.6 1.6,1.6, height 1.55
Epson_FC-12M [mm] "Epson"
  rect 0.7x1.4 smd: 1(-0.75,0) 2(0.75,0)
  body extent -1.05,-0.63 1.05,0.63, height 0.6
Fiducial10-20 [mm]
  round 1 smd mask+0.5: 1(0,0)
  Top Layer keep-out circle w1.178: c0,0 r0.5
Keystone_1902C [mil] "Hex Standoff, 4-40 threaded, nylon"
  round 1 on Mech4: 0(0,0)
  body extent -145,-126 146,126, height 501
Keystone_2462 [mm] "2x AA Battery Holder, Through-hole mount"
  rect 1.8x1.8 hole 1.27: 1(-13.59,7.495)
  round 1.8 hole 1.27: 2(-13.59,-7.495)
  round 4.05 hole 3.55: 3(13.59,-7.495) 4(13.59,7.495)
  silkscreen extent -16.18,-16.46 43.33,16.46, body extent -16.31,-16.46 43.4,16.46, height 16
LGA-12P [mm]
  rect 0.3x0.35 smd mask+0.05: 1(-0.75,-0.775) 2(-0.25,-0.775) 3(0.25,-0.775) 4(0.75,-0.775) 7(0.75,0.775) 8(0.25,0.775) 9(-0.25,0.775) 10(-0.75,0.775)
  rect 0.35x0.3 smd mask+0.05: 5(0.775,-0.25) 6(0.775,0.25) 11(-0.775,0.25) 12(-0.775,-0.25)
  silkscreen extent -1.8,-1.8 -1.29,-1.3
MF03A_N [mm] "SOT23, 3-Leads, Body 2.9x1.3mm, Pitch 0.95mm, Lead Span 2.4mm, IPC Medium Density"
  rect 1.3x0.6 smd: 1(-1.05,0.95) 2(-1.05,-0.95) 3(1.05,0)
  silkscreen extent -1.18,-1.5 0.7,1.92, body extent -0.7,-1.5 0.7,1.5, height 1.12
MF05A_L [mm] "SOT23, 5-Leads, Body 2.9x1.6mm, Pitch 0.95mm, Lead Span 2.8mm, IPC High Density"
  rect 0.9x0.65 smd: 1(-1.2,0.95) 2(-1.2,0) 3(-1.2,-0.95) 4(1.2,-0.95) 5(1.2,0.95)
  silkscreen extent -1.32,-1.55 0.35,1.95, body extent -0.9,-1.55 0.9,1.55, height 1.19
NORCOMP_182-009-213R171 [mm] "Connector; D Subminiature 9 Position; Right Angle"
  rect 1.8x1.8 hole 1.092: 1(-5.54,-10.92)
  round 1.8 hole 1.092: 2(-2.77,-10.92) 3(0,-10.92) 4(2.77,-10.92) 5(5.54,-10.92) 6(-4.155,-8.08) 7(-1.385,-8.08) 8(1.385,-8.08) 9(4.155,-8.08)
  round 4.76 hole 3.05: 10(-12.495,-9.5) 11(12.495,-9.5)
  silkscreen extent -15.4,-12.4 15.4,6, body extent -15.41,-12.98 15.41,6.1, height 12.55
"NY PMS 440 0025 PH" [mm] "4-40 nylon screw and mounting hole"
  round 8 hole 3.2: 1(0,0)
  body extent -3.3,-3.3 3.3,3.3, height 2.69
PBS0032A_N [mil]
  rect 60x9 smd: 1(-124,68.9) 2(-124,49.21) 3(-124,29.53) 4(-124,9.84) 5(-124,-9.84) 6(-124,-29.53) 7(-124,-49.21) 8(-124,-68.9) 17(124,-68.9) 18(124,-49.21) 19(124,-29.53) 20(124,-9.84) 21(124,9.84) 22(124,29.53) 23(124,49.21) 24(124,68.9)
  rect 9x60 smd: 9(-68.9,-124) 10(-49.21,-124) 11(-29.53,-124) 12(-9.84,-124) 13(9.84,-124) 14(29.53,-124) 15(49.21,-124) 16(68.9,-124) 25(68.9,124) 26(49.21,124) 27(29.53,124) 28(9.84,124) 29(-9.84,124) 30(-29.53,124) 31(-49.21,124) 32(-68.9,124)
  silkscreen extent -104,-100 100,104, body extent -140,-140 140,140, height 48
PogoPad [mil] "No Solder Paste"
  round 70 smd paste-35: 1(0,0)
PW0014A_M [mm] "TSOP, 14-Leads, Body 5x4.4mm, Pitch 0.65mm, IPC Low Density"
  oval 2x0.35 smd: 1(-2.9,1.95) 2(-2.9,1.3) 3(-2.9,0.65) 4(-2.9,0) 5(-2.9,-0.65) 6(-2.9,-1.3) 7(-2.9,-1.95) 8(2.9,-1.95) 9(2.9,-1.3) 10(2.9,-0.65) 11(2.9,0) 12(2.9,0.65) 13(2.9,1.3) 14(2.9,1.95)
  silkscreen extent -1.5,-2.55 1.53,2.55, body extent -3.21,-2.5 3.21,2.5, height 0.98
RGC0064B [mm]
  oval 0.6x0.24 smd mask+0.07: 1(-4.4,3.75) 2(-4.4,3.25) 3(-4.4,2.75) 4(-4.4,2.25) 5(-4.4,1.75) 6(-4.4,1.25) 7(-4.4,0.75) 8(-4.4,0.25) 9(-4.4,-0.25) 10(-4.4,-0.75) 11(-4.4,-1.25) 12(-4.4,-1.75) 13(-4.4,-2.25) 14(-4.4,-2.75) 15(-4.4,-3.25) 16(-4.4,-3.75) 33(4.4,-3.75) 34(4.4,-3.25) 35(4.4,-2.75) 36(4.4,-2.25) 37(4.4,-1.75) 38(4.4,-1.25) 39(4.4,-0.75) 40(4.4,-0.25) 41(4.4,0.25) 42(4.4,0.75) 43(4.4,1.25) 44(4.4,1.75) 45(4.4,2.25) 46(4.4,2.75) 47(4.4,3.25) 48(4.4,3.75)
  oval 0.24x0.6 smd mask+0.07: 17(-3.751,-4.4) 18(-3.251,-4.4) 19(-2.751,-4.4) 20(-2.251,-4.4) 21(-1.75,-4.4) 22(-1.25,-4.4) 23(-0.75,-4.4) 24(-0.25,-4.4) 25(0.25,-4.4) 26(0.75,-4.4) 27(1.25,-4.4) 28(1.75,-4.4) 29(2.251,-4.4) 30(2.751,-4.4) 31(3.251,-4.4) 32(3.751,-4.4) 49(3.751,4.4) 50(3.251,4.4) 51(2.751,4.4) 52(2.251,4.4) 53(1.75,4.4) 54(1.25,4.4) 55(0.75,4.4) 56(0.25,4.4) 57(-0.25,4.4) 58(-0.75,4.4) 59(-1.25,4.4) 60(-1.75,4.4) 61(-2.251,4.4) 62(-2.751,4.4) 63(-3.251,4.4) 64(-3.751,4.4)
  rect 4.25x4.25 smd paste-2.112: 65(0,0)
  silkscreen extent -5.1,-5.1 5.1,5.1, body extent -4.57,-4.57 4.57,4.57, height 1.01
SOD-523F [mm] "COMCHIP"
  rect 0.6x0.8 smd paste-0.05: 1(-0.85,0) 2(0.85,0)
  silkscreen extent -1.92,-0.87 1.1,0.88, body extent -0.9,-0.5 0.9,0.5, height 0.85
TC2030-MCP-NL [mil] "TAG-CONNECT"
  round 31 smd paste-16: 1(-25,-50) 2(25,-50) 3(-25,0) 4(25,0) 5(-25,50) 6(25,50)
  round 25 hole 39 unplated: MH1(0,-100) MH2(-40,100) MH3(40,100)
  silkscreen extent -122,-195 118,195
TI_Symbol_Overlay_Small [mm]
  silkscreen extent -2.3,-2.23 2.3,2.24
TP_25MIL-SMT#1 [mm]
  round 0.635 smd mask-0.064: 1(0,0)
TP_25MIL-SMT#2 [mm]
  round 0.535 smd mask-0.064: 1(0,0)
TP_SM_1MM#1 [mm] "1mm Test Point, SMT"
  rrect50% 10x18 smd paste-0.5: 1(0,0)
TP_SM_1MM#2 [mm] "1mm Test Point, SMT"
  rrect50% 18x10 smd paste-0.5: 1(0,0)
TP_SM_1MM#3 [mm] "1mm Test Point, SMT"
  round 1 smd paste-0.5: 1(0,0)
Wurth_61201420621 [mm] "Header, 2.54mm, 7x2, SMT"
  rect 4x0.9 smd: 1(-3,7.62) 2(3,7.62) 3(-3,5.08) 4(3,5.08) 5(-3,2.54) 6(3,2.54) 7(-3,0) 8(3,0) 9(-3,-2.54) 10(3,-2.54) 11(-3,-5.08) 12(3,-5.08) 13(-3,-7.62) 14(3,-7.62)
  silkscreen extent -4.75,-12.7 4.4,12.7, body extent -4.75,-12.7 4.75,12.7, height 10.43

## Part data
1 2 3 4 5 6 7 8 9 10 11 12 13 14 15: "Test Point, O.025\""
BT3 BT4: "2x AA Battery Holder, Through-hole mount"
C1 C2 C12: "CAP, TA, 10 µF, 10 V, +/- 10%, 3.4 ohm, SMD"
C3 C6 C7 C10 C11 C13 C14 C18 C19 C23 C24 C28 C36 C37 C40 C42 C48 C50 C52: "CAP, CERM, 0.1 µF, 10 V, +/- 10%, X5R, 0402"
C4 C27: "CAP, CERM, 1 µF, 6.3 V, +/- 20%, X5R, 0402"
C5 C20: "CAP, CERM, 2.2 µF, 16 V, +/- 10%, X5R, 0402"
C8 C26 C38: "CAP, CERM, 0.01 µF, 25 V, +/- 10%, X7R, 0402"
C9 C15: "CAP, TA, 1 µF, 16 V, +/- 10%, 9.3 ohm, SMD"
C16 C17 C21 C22 C34 C35: "CAP, CERM, 10 µF, 6.3 V, +/- 20%, X5R, 0402"
C25 C46 C49 C53 C54: "CAP, CERM, 2200 pF, 50 V, +/- 10%, X8R, 0402"
C29: "CAP, CERM, 0.47 µF, 6.3 V, +/- 10%, X5R, 0402"
C30: "CAP, CERM, 33 pF, 50 V, +/- 5%, C0G/NP0, 0603"
C31: "CAP, CERM, 39pF, 50V, +/-5%, C0G/NP0, 0402"
C32: "CAP, CERM, 100 µF, 10 V, +/- 20%, X5R, 1206_190"
C33: library part Capacitor, "CAP, CERM, xxxF, xxV, [TempCo], xx%, [PackageReference]"
C39 C41 C55 C56: "CAP, CERM, 1 µF, 16 V, +/- 10%, X5R, 0402"
C43: "CAP, CERM, 1500 pF, 50 V, +/- 10%, X7R, 0603"
C44 C57: "CAP, CERM, 3000 pF, 50 V, +/- 5%, C0G/NP0, 0603"
C45 C47: "CAP, CERM, 4700 pF, 10 V, +/- 10%, X5R, 0402"
C51: "CAP, CERM, 10 µF, 6.3 V, +/- 20%, X5R, 0603"
C58 C59: "CAP, CERM, 10 pF, 50 V, +/- 5%, C0G/NP0, 0603"
D1 D2: "Diode, Schottky, 35V, 0.1A, SOD-523F"
FID1 FID2 FID3: "Fiducial mark.  There is nothing to buy or mount."
H1 H2 H3 H4: "Bumpon, Hemisphere, 0.375 X 0.235, Black"
H5 H6 H7 H8: "Machine Screw, Round, #4-40 x 1/4, Nylon, Philips panhead"
H9 H10 H11 H12: "Standoff, Hex, 0.5\"L #4-40 Nylon"
J1: "Footprint for TC2030-MCP-NL"
J2: "Header(Shrouded), 2.54mm, 7x2, Gold, Black, SMT"
J3: "CONN DB9 FEMALE R/A SOLDER TH"
L1 L2 L3 L4 L5 L6: "Ferrite Bead, 600 ohm @ 100MHz, 0.2A, 0603"
L7: "Inductor, Shielded, Ferrite, 4.7uH, 1.2A, 0.14 ohm, SMD"
Logo1: library part TI_Logo, "Texas Instrument Corporate Signature"
R1 R2 R3 R4 R5 R7 R13 R14 R16 R19: "RES, 0, 5%, 0.063 W, 0402"
R6: "RES, 47 k, 5%, 0.063 W, 0402"
R8: "RES, 21.5 k, 1%, 0.063 W, 0402"
R9: "RES, 10.0 k, 1%, 0.063 W, 0402"
R10 R15 R20: "RES, 1.00 M, 1%, 0.1 W, 0402"
R11: "RES, 11.8 k, 1%, 0.063 W, 0402"
R12: "RES, 8.06 k, 1%, 0.063 W, 0402"
R17: "RES, 200 k, 1%, 0.1 W, 0402"
R18: "RES, 4.99 k, 1%, 0.063 W, 0402"
R21 R22: "RES, 100 k, 1%, 0.1 W, 0402"
R23 R30: "RES, 51.1 k, 1%, 0.063 W, 0402"
R24 R25 R28 R29: "RES, 10.0 M, 1%, 0.063 W, 0402"
R26 R27: "RES, 40.2 k, 1%, 0.063 W, 0402"
R31 R32: "RES, 3.3 k, 5%, 0.063 W, 0402"
TP1 TP2 TP3 TP4 TP5: library part TP_SM_1MM, "1mm Test Point, SMT"
TP6: library part PogoPad, "Pad for Pogo Pin Connector"
U1: "Single Output High PSRR LDO, 200 mA, Fixed 3 V Output, 2.7 to 5.5 V Input, 5-pin SOT-23 (DBV), -40 to 85 degC, Green (RoHS & no Sb/Br)"
U2: "Single Micropower Precision Op Amp"
U3: "Precision Micropower Shunt Voltage Reference, 3-pin SOT-23"
U4: library part RF430CL331H, "The Texas Instruments Dynamic NFC Interface Transponder RF430CL331H is an NFC Tag Type 4 device  that combines a wireless NFC interface and a wired SPI or I2C interface to connect the device to a host."
U5: "LOW INPUT VOLTAGE STEP-UP CONVERTER IN 6 PIN SC-70 PACKAGE, DCK0006A"
U6: library part BMA250, "14 bit, digital, triaxial acceleration sensor with intelligent on-chip motion triggered interrupt controller"
U7: "High-Accuracy, Low-Power, Digital Temperature Sensor With SMBus(TM)/Two-Wire Serial Interface, DRL0006A"
U8: "Low-Power, 2-Channel, 24-Bit Analog Front-End for Biopotential Measurement, PBS0032A"
U9: "Mixed-Signal Microcontrollers, RGC0064B"
Y1: "Crystal, 32.768kHz, 12.5pF, SMD"
ZZ1: library part AssemblyNoteLabel
ZZ2 ZZ3 ZZ4: library part AssemblyNote

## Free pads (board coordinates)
  round 0 hole 3.762 unplated: 0(87.681,88.062)

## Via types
v1: diameter 0.864, hole 0.406, Top Layer to Bottom Layer, 104 vias
v2: diameter 0.5, hole 0.2, Top Layer to Bottom Layer, 13 vias

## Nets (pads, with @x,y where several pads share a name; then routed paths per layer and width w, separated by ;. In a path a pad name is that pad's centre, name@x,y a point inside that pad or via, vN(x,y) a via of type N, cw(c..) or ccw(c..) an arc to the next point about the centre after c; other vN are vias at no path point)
3V: C3.1 C4.1 C35.1 R4.2 R5.2 R15.2 U1.1 U1.3 U5.4 | length 53.6
  Top Layer w0.254: U1.3@92.919,102.55 U1.3@92.997,102.628 ; 94.158,100.178 94.259,100.178 ; C3.1@94.441,102.55 C3.1@94.518,102.628 ; 96.434,106.02 96.434,106.061
  Top Layer w0.54: R15.2@92.786,104.496 96.434,104.496 ; U1.1@92.919,100.65 93.685,100.65 94.158,100.178 ; U1.3@92.919,102.55 C3.1@94.441,102.55 ; 94.259,100.178 97.612,100.178 98.12,100.686 98.12,101.702 95.672,104.15 96.434,104.496 ; C3.1@94.518,102.628 C4.1@95.788,102.628 95.788,104.034 ; U5.4@95.417,109.662 95.417,110.632 95.783,110.998 97.257,110.998 97.765,110.49 ; C35.1@95.621,105.41 96.434,105.41 ; 96.434,106.02 96.434,105.41 ; 96.434,106.061 97.053,106.68 97.053,107.696 97.358,108.001 97.358,110.084 97.765,110.49 ; v1(100.406,113.132) 97.765,110.49 ; v1(102.946,115.672) 105.74,115.672 112.532,122.463 R5.2@112.532,124.816 ; R4.2@112.512,126.365 112.532,126.346 R5.2@112.532,124.861 ; 96.434,104.496 96.434,105.41
  Bottom Layer w0.54: v1(100.406,113.132) v1(102.946,115.672)
ADS1292_DRDY: 9.1 U8.22 U9.16 | length 19.6
  Top Layer w0.254: U8.22@89.218,138.704 89.218,137.039 89.484,136.773 v1(89.484,136.754) ; U9.16@94.392,128.312 v1(95.774,128.312) 96.088,127.998 9.1@96.088,127.356
  Bottom Layer w0.254: v1(89.484,136.754) 89.484,134.602 93.428,130.658 ; 93.428,130.658 v1(95.774,128.312) 95.774,129.448 94.564,130.658 93.428,130.658
ADS1292_ELA: C52.1 J3.2 R30.1 TP4.1 | length 93.4
  Top Layer w1: R30.1@83.537,151.409 83.537,154.733 ; J3.2@87.298,160.454 87.3,157.302 ; C52.1@93.294,152.086 93.294,153.518 92.024,154.788 83.537,154.733 ; TP4.1@145.034,143.358 145.034,153.822 141.554,157.302 88.468,157.302 84.811,157.302 83.537,156.028 83.537,154.733
ADS1292_ERA: C48.1 J3.1 R23.1 TP3.1 | length 92.4
  Top Layer w0.54: R23.1@84.811,151.437 v1@84.811,153.67
  Top Layer w1: TP3.1@28.6,143.358 28.6,153.822 31.191,156.413 78.842,156.413 82.882,160.454 J3.1@84.528,160.454 ; v1(94.513,155.143) 94.564,155.092 C48.1@94.564,152.086
  Bottom Layer w0.54: v1@84.811,153.67 85.623,154.534
  Bottom Layer w1: J3.1@84.528,160.454 84.528,156.873 84.811,156.591 84.811,153.67 v1(84.811,153.314) ; 85.014,155.143 v1(94.513,155.143)
ADS1292_GPIO1: 6.1 U8.26 U9.14 | length 24.5
  Top Layer w0.254: U8.26@91.618,140.603 93.001,140.603 94.515,139.089 94.515,137.976 96.499,135.992 ; U9.14@94.392,127.312 95.116,127.312 96.838,125.59 v1@96.838,125.336 ; 6.1@95.072,131.674 95.943,131.674 v1(96.349,132.08) 96.505,132.236 96.505,135.992
  Bottom Layer w0.254: v1(96.349,132.08) 98.374,130.055 98.374,126.848 v1(96.85,125.324)
ADS1292_GPIO2: 7.1 U8.25 U9.25 | length 20.5
  Top Layer w0.254: U9.25@89.742,128.962 89.742,129.729 ; 89.741,129.73 89.741,131.626 90.957,132.842 95.529,132.842 96.088,133.401 96.088,135.839 94.061,137.866 94.061,138.8 92.758,140.103 U8.25@91.618,140.103 ; 89.741,131.166 7.1@91.262,131.166
ADS1292_IN1N: C46.1 R24.1 R25.2 U8.3 | length 12.8
  Top Layer w0.254: R24.1@89.068,152.202 89.738,152.202 ; U8.3@89.218,145.003 89.218,148.184 89.484,148.45 v1(89.484,148.946) ; 89.294,147.753 89.977,147.753 C46.1@90.662,148.438 ; v1(89.738,153.264) 89.738,152.202 ; R25.2@90.662,152.202 89.738,152.202
  Bottom Layer w0.254: v1(89.484,148.946) 89.484,150.932 89.738,151.186 v1(89.738,153.264)
ADS1292_IN1P: C54.1 R28.1 R29.2 U8.4 | length 9.1
  Top Layer w0.254: U8.4@88.718,145.003 88.718,149.246 89.179,149.708 C54.1@90.662,149.708 ; R28.1@89.068,150.932 89.865,150.932 ; 89.865,149.835 89.865,150.932 ; R29.2@90.662,150.932 89.865,150.932
ADS1292_IN2N: C44.1 R23.2 U8.5 | length 8.7
  Top Layer w0.254: C44.1@86.335,150.291 84.865,150.291 R23.2@84.811,150.237 84.811,149.447 85.166,149.092 86.05,149.092 86.335,148.807 88.218,146.924 U8.5@88.218,145.003
ADS1292_IN2P: C57.1 R30.2 U8.6 | length 9.5
  Top Layer w0.254: C57.1@82.013,150.263 83.483,150.263 R30.2@83.537,150.209 ; R30.2@83.483,150.209 83.483,149.359 84.204,148.638 85.862,148.638 87.718,146.782 U8.6@87.718,145.003
ADS1292_MAIN_CLKSEL: 14.1 U8.14 U9.32 | length 17.1
  Top Layer w0.254: U8.14@85.319,141.103 83.908,141.103 83.242,140.437 83.242,130.658 83.75,130.15 85.928,130.15 ; 14.1@85.928,130.912 85.928,130.15 ; U9.32@86.241,128.962 86.241,129.837 85.928,130.15
ADS1292_RESET: 8.1 U8.15 U9.31 | length 16.9
  Top Layer w0.254: 8.1@85.166,132.944 85.166,131.597 ; U8.15@85.319,140.603 85.299,140.583 84.204,140.583 83.696,140.075 83.696,132.128 84.227,131.597 85.166,131.597 ; U9.31@86.741,128.962 86.741,131.368 86.513,131.597 85.166,131.597
ADS1292_RESP_MODP/IN3N: R26.2 U8.32 | length 2.4
  Top Layer w0.254: U8.32@91.618,143.603 93.286,143.603 93.294,143.612 R26.2@93.294,144.328
ADS1292_RESP_MODP/IN3P: R27.2 TP6.1 U8.31 | length 13.4
  Top Layer w0.254: U8.31@91.618,143.103 93.34,143.103 R27.2@94.564,144.328 97.566,144.328 98.374,145.136 TP6.1@98.374,150.901
ADS1292_RLD: J3.4 R22.2 TP5.1 | length 3.2
  Top Layer w0.254: R22.2@103.038,147.168 104.724,147.168 v1(105.232,146.66)
  Bottom Layer w0.254: v1(105.232,146.66) 105.766,146.126
ADS1292_SPI_CS: 10.1 U8.18 U9.29 | length 14.1
  Top Layer w0.254: 85.258,135.23 10.1@86.436,135.23 ; 87.172,137.328 86.385,136.541 85.766,136.541 85.166,135.941 85.166,134.722 85.42,134.468 87.045,134.468 87.742,133.771 U9.29@87.742,128.962 ; 87.218,137.374 U8.18@87.218,138.704
ADS1292_SPI_DIN: 12.1 U8.19 U9.26 | length 17.3
  Top Layer w0.254: 12.1@81.864,135.23 81.864,135.992 82.118,136.246 v1(82.118,136.5) ; v1@87.718,136.766 U8.19@87.718,138.704 ; U9.26@89.242,128.962 89.242,132.143 v1(89.687,132.588)
  Bottom Layer w0.254: v1(82.118,136.5) v1(87.452,136.5) 87.452,134.823 v1(89.687,132.588)
ADS1292_SPI_DOUT: 11.1 U8.21 U9.27 | length 29.7
  Top Layer w0.254: U9.27@88.742,128.962 88.742,134.074 88.718,134.098 U8.21@88.718,138.704 88.718,140.052 v1(89.484,140.818) ; v1(99.898,147.93) 99.898,149.2 11.1@101.93,151.232
  Bottom Layer w0.254: v1(89.484,140.818) 93.548,144.882 96.85,144.882 v1(99.898,147.93)
ADS1292_SPI_SCLK: 13.1 U8.20 U9.28 | length 21.9
  Top Layer w0.254: 13.1@81.813,147.32 82.575,146.558 84.099,146.558 v1(84.607,146.05) ; v1(87.706,140.31) 88.214,139.802 88.214,133.96 88.242,133.932 U9.28@88.242,128.962
  Bottom Layer w0.254: v1(84.607,146.05) 84.607,143.408 v1(87.706,140.31)
ADS1292_START: 15.1 U8.16 U9.30 | length 15.2
  Top Layer w0.254: 84.15,137.77 15.1@84.912,137.77 ; U8.16@85.319,140.103 84.432,140.103 84.15,139.821 84.15,138.204 84.15,134.722 84.912,133.96 86.69,133.96 87.242,133.408 U9.30@87.242,128.962
ADS1292_VCAP1: C55.1 U8.11 | length 4.6
  Top Layer w0.254: C55.1@80.74,142.603 U8.11@85.319,142.603
ADS1292_VCAP2: C56.1 U8.27 | length 6.8
  Top Layer w0.254: U8.27@91.618,141.103 93.416,141.103 94.969,139.55 94.969,138.022 95.476,137.516 C56.1@95.996,137.516
ADS1292_VREFP: C50.1 C51.1 U8.9 | length 5.9
  Top Layer w0.254: C51.1@81.601,145.58 C51.1@81.305,145.58 81.413,145.472 C50.1@82.829,145.472 83.661,145.472 83.845,145.288 83.845,144.018 84.26,143.603 U8.9@85.319,143.603
ADS_AVCC: C22.1 C23.1 C24.1 C39.1 C40.1 L6.2 R8.2 R24.2 R28.2 U2.5 U8.12 | length 21.4
  Top Layer w0.254: U2.5@76.068,143.8 77.023,143.8 77.241,144.018 v1(77.241,144.78) ; v1(76.479,145.542) 76.528,145.493 77.701,145.493 78.308,146.101 R8.2@78.308,147.33 ; v1(78.257,136.906) 78.621,137.27 79.474,137.27 C23.1@79.532,137.212 ; v1(78.85,141.106) C39.1@80.802,141.106 ; L6.2@79.578,135.522 79.578,137.166 C23.1@79.532,137.212 ; v1(80.594,148.184) C24.1@80.594,150.378 ; C22.1@80.802,137.212 C23.1@79.532,137.212 ; C39.1@81.102,141.164 C40.1@82.372,141.164 83.312,142.103 U8.12@85.319,142.103 ; v1(87.868,149.362) R28.2@87.868,150.932 R24.2@87.868,152.202
ADS_AVSS: C22.2 C23.2 C24.2 C39.2 C40.2 C44.2 C50.2 C51.2 C55.2 C56.2 C57.2 J3.10 J3.11 R3.2 R9.1 R12.1 R25.1 R29.1 U2.2 U3.2 U8.10 U8.13 | length 43.8
  Top Layer w0.254: v1(67.977,123.489) R3.2@69.793,123.489 ; v1(72.582,142.85) U2.2@73.668,142.85 ; R12.1@75.723,148.117 74.752,149.088 74.752,151.74 75.448,152.436 78.7,152.436 80.528,152.436 ; v1@77.8,143.612 v1(78.054,143.612) 78.054,143.205 78.664,142.596 C55.2@79.532,142.596 ; v1(79.781,146.304) 79.781,144.272 80.073,143.98 C51.2@81.305,143.98 81.597,144.272 C50.2@82.829,144.272 82.829,143.51 83.236,143.104 83.845,143.104 U8.10@85.319,143.103 ; C24.2@80.594,151.578 v1(80.594,153.518) ; C22.2@80.802,138.412 79.532,138.412 79.532,139.906 80.802,139.906 81.968,139.906 C40.2@82.199,140.137 ; C57.2@82.013,151.863 v1(82.013,153.496) ; C40.2@82.372,139.964 82.372,140.068 83.666,141.362 ; 83.666,141.373 83.896,141.603 U8.13@85.319,141.603 ; C44.2@86.335,151.891 v1(86.335,153.416) ; R29.1@91.862,150.932 R25.1@91.862,152.202 v1(91.862,153.426) ; C56.2@97.196,137.516 97.196,136.916 v1(97.612,136.5)
  Top Layer w0.54: v1(103.962,135.484) R9.1@103.962,137.17
  other v1: 79.832,139.906
ADS_DVCC: C15.1 C19.1 C20.1 C21.1 C41.1 C42.1 L5.2 L6.1 U8.23 | length 24.7
  Top Layer w0.254: L6.1@79.578,133.972 79.832,133.972 v1(79.832,132.436) ; 89.484,135.484 89.484,134.376 89.738,134.122 C42.1@90.5,134.122 C41.1@91.77,134.122 C19.1@93.04,134.122 C20.1@94.31,134.122 ; 89.501,135.5 90.246,136.246 90.246,137.008 89.718,137.536 U8.23@89.718,138.704 ; C20.1@94.339,134.15 C20.1@94.31,134.122 ; v1(95.275,133.858) 95.275,133.896 95.05,134.122 C20.1@94.31,134.122 ; v1(97.612,132.944) C21.1@97.612,134.122 98.282,133.452 L5.2@99.606,133.452 99.606,134.176 100.66,135.23 100.66,139.294 99.898,140.056 C15.1@99.898,141.296
ANTENNA: D1.2 D2.2 R13.2 R14.2 | length 600.2
  Top Layer w0.4: v1(77.038,95.86) 77.8,96.622 98.628,96.622 98.628,73 76.276,73 76.276,97.13 99.136,97.13 99.136,72.492 75.768,72.492 75.768,97.638 99.644,97.638 99.644,71.984 75.209,71.984 75.209,98.044 76.022,98.857 76.022,103.631 76.578,104.055 77.669,104.055 ; v1(77.038,100.178) 77.038,101.702 77.648,102.311 84.404,102.311 84.734,102.641 D2.2@84.734,103.239 ; D1.2@77.669,106.379 77.669,104.055 ; R13.2@79.447,104.055 77.669,104.055 ; 80.971,102.311 R14.2@80.971,104.055
  Bottom Layer w0.4: 75.209,97.079 75.209,71.984 99.644,71.984 99.644,97.638 77.038,97.638 v1(77.038,100.178) ; 75.26,97.13 99.136,97.13 99.136,72.492 75.768,72.492 75.768,96.622 98.628,96.622 98.628,73 76.276,73 76.276,95.098 v1(77.038,95.86)
BMA_AVCC: C16.1 C37.1 L4.1 U6.7 | length 5.4
  Top Layer w0.254: C16.1@73.99,128.647 C37.1@75.26,128.647 ; U6.7@74.993,127.111 74.993,128.38 C37.1@75.26,128.647 ; L4.1@76.746,129.896 76.746,129.045 76.507,128.805 75.419,128.805 C37.1@75.26,128.647
BMA_DVCC: C17.1 C36.1 L3.2 L4.2 U6.1 U6.3 U6.11 | length 28.6
  Top Layer w0.254: U6.11@75.518,125.586 75.518,124.794 75.235,124.511 73.889,124.511 72.619,125.781 72.619,129.616 74.117,131.115 77.978,131.115 78.346,130.747 L4.2@78.346,129.896 78.346,129.096 79.324,128.118 L3.2@80.302,128.118 80.34,128.08 C17.1@80.34,126.224 C36.1@79.07,126.224 78.683,126.611 U6.3@76.543,126.611 ; U6.1@76.543,125.611 76.543,125.158 76.987,124.714 77.851,124.714 78.334,125.197 78.334,126.585
BMA_INT1: U6.5 U9.38 | length 11
  Top Layer w0.254: U6.5@76.018,127.136 76.018,127.657 76.153,127.792 v1(76.629,127.792) ; v1(82.118,126.848) 83.134,125.832 ; 83.154,125.812 U9.38@85.592,125.812
  Bottom Layer w0.254: v1(76.629,127.792) 77.597,127.792 78.616,126.774 79.162,126.774 79.235,126.848 v1(82.118,126.848)
BMA_INT2: U6.6 U9.33 | length 12.2
  Top Layer w0.254: U6.6@75.518,127.136 75.518,127.88 76.09,128.451 77.165,128.451 77.492,128.778 v1(77.572,128.778) ; v1(83.845,129.286) 83.845,128.676 84.21,128.312 U9.33@85.592,128.312
  Bottom Layer w0.254: v1(77.572,128.778) 83.337,128.778 v1(83.845,129.286)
